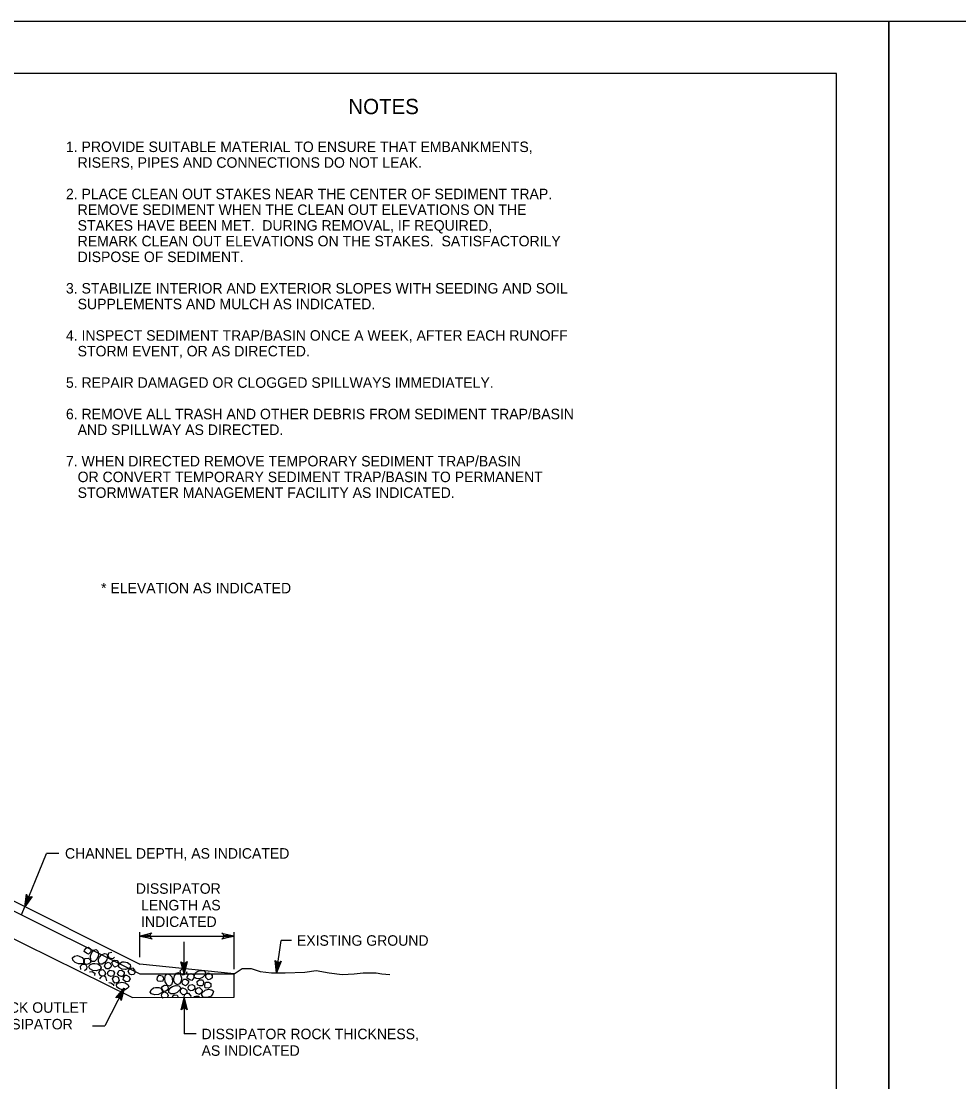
# Model space of a CAD drawing. Extents: x 636462 to 639890, y 299944 to 300538.
# Drawn here: x 637895.9 to 638163.9, y 300235 to 300538.4 of the extents above; entities that cross this region are included whole.
import ezdxf

# ---------------------------------------------------------------- set-up
doc = ezdxf.new("R2010")
doc.units = 0
for name, color, linetype in [('1', 7, 'Continuous'), ('Default', 7, 'Continuous'), ('PLT-BNDY', 7, 'Continuous')]:
    doc.layers.add(name, color=color, linetype=linetype)

msp = doc.modelspace()

# ---------------------------------------------------------------- linework, layer by layer
at = {"layer": '1'}
msp.add_lwpolyline([(638128.91, 299959.45), (638128.91, 300523.45), (637342.91, 300523.45), (637342.91, 299959.45), (638128.91, 299959.45), (638128.91, 299985.81), (637928.91, 299985.81), (637928.91, 300050.49), (638128.91, 300050.49), (638128.91, 300079.45), (637928.91, 300079.45), (637928.91, 299959.45), (638007.72, 299959.45), (638007.72, 299985.81), (638007.72, 299959.45), (638084.72, 299959.45), (638084.72, 299985.81), (638084.72, 299973.49), (638128.91, 299973.49)], dxfattribs=at)
at = {"layer": 'Default'}
for p, q in [((637788.44, 300339.34), (637929.75, 300268.68)), ((637804.16, 300328.69), (637929.74, 300265.89)), ((637801.63, 300321.37), (637927.67, 300259.18)), ((637895.93, 300282.8), (637903.13, 300300.35)), ((637906.63, 300300.35), (637903.13, 300300.35)), ((637929.75, 300270.69), (637929.75, 300277.85)), ((637929.75, 300276.72), (637956.7, 300276.72)), ((637956.7, 300267.25), (637956.7, 300277.85)), ((637913.9, 300272.27), (637913.95, 300272.69)), ((637913.95, 300272.69), (637914.39, 300273.28)), ((637914.39, 300273.28), (637915.06, 300273.51)), ((637915.06, 300273.51), (637915.8, 300272.95)), ((637915.8, 300272.95), (637915.76, 300272.19)), ((637916, 300271.97), (637916.64, 300272.69)), ((637916.64, 300272.69), (637917.28, 300272.83)), ((637917.28, 300272.83), (637917.77, 300272.36)), ((637942.42, 300265.89), (637942.42, 300275.03)), ((637968.83, 300266.17), (637970.18, 300275.44)), ((637973.18, 300275.44), (637970.18, 300275.44)), ((637910.51, 300270.5), (637911.07, 300270.95)), ((637910.62, 300269.84), (637910.51, 300270.5)), ((637911.29, 300269.19), (637910.62, 300269.84)), ((637911.07, 300270.95), (637911.94, 300271.13)), ((637911.94, 300271.13), (637912.45, 300270.98)), ((637912.45, 300270.98), (637913.29, 300270.55)), ((637913.29, 300270.55), (637913.89, 300269.81)), ((637913.76, 300269.1), (637913.8, 300269.73)), ((637913.8, 300269.73), (637914.1, 300270.26)), ((637913.89, 300269.81), (637913.88, 300269.18)), ((637914.52, 300271.78), (637913.9, 300272.27)), ((637914.1, 300270.26), (637915.05, 300270.36)), ((637915.13, 300271.52), (637914.52, 300271.78)), ((637915.05, 300270.36), (637915.62, 300269.86)), ((637915.76, 300272.19), (637915.13, 300271.52)), ((637915.62, 300269.86), (637915.65, 300269.04)), ((637915.66, 300271.04), (637916, 300271.97)), ((637915.8, 300269.82), (637915.66, 300271.04)), ((637916.18, 300269.4), (637915.8, 300269.82)), ((637916.82, 300269.46), (637916.18, 300269.4)), ((637917.5, 300270.13), (637916.82, 300269.46)), ((637917.88, 300270.95), (637917.5, 300270.13)), ((637917.77, 300272.36), (637918, 300271.48)), ((637918, 300271.48), (637917.88, 300270.95)), ((637917.96, 300270.11), (637918.25, 300270.64)), ((637917.98, 300269.29), (637917.96, 300270.11)), ((637918.25, 300270.64), (637918.85, 300271.34)), ((637918.85, 300271.34), (637919.67, 300271.75)), ((637919.67, 300271.75), (637920.28, 300271.58)), ((637920.34, 300269.9), (637919.75, 300269.11)), ((637920.28, 300271.58), (637920.54, 300271.09)), ((637920.54, 300271.09), (637920.34, 300269.9)), ((637920.7, 300271.01), (637920.93, 300271.87)), ((637921.1, 300270.36), (637920.7, 300271.01)), ((637920.93, 300271.87), (637921.72, 300272.07)), ((637922.07, 300270.24), (637921.1, 300270.36)), ((637921.9, 300269.33), (637922.57, 300269.78)), ((637922.5, 300270.65), (637922.07, 300270.24)), ((637922.57, 300269.78), (637923.32, 300269.71)), ((637923.32, 300269.71), (637923.78, 300268.95)), ((637912.23, 300268.76), (637911.29, 300269.19)), ((637913.43, 300268.8), (637912.23, 300268.76)), ((637912.84, 300268.07), (637913.37, 300268.64)), ((637912.86, 300267.18), (637912.84, 300268.07)), ((637913.37, 300268.64), (637914.19, 300268.64)), ((637913.88, 300269.18), (637913.43, 300268.8)), ((637914.31, 300268.62), (637913.76, 300269.1)), ((637914.55, 300267.26), (637913.99, 300266.72)), ((637914.19, 300268.64), (637914.59, 300267.93)), ((637914.95, 300268.63), (637914.31, 300268.62)), ((637914.59, 300267.93), (637914.55, 300267.26)), ((637915.65, 300269.04), (637914.95, 300268.63)), ((637915.17, 300267.89), (637915.52, 300268.49)), ((637915.45, 300267.31), (637915.17, 300267.89)), ((637915.4, 300266.43), (637916.14, 300266.57)), ((637916.3, 300266.85), (637915.45, 300267.31)), ((637915.52, 300268.49), (637916.32, 300268.9)), ((637916.14, 300266.57), (637916.94, 300266.1)), ((637917.28, 300266.72), (637916.3, 300266.85)), ((637916.32, 300268.9), (637916.87, 300268.9)), ((637916.87, 300268.9), (637917.76, 300268.72)), ((637918.44, 300267.13), (637917.28, 300266.72)), ((637917.76, 300268.72), (637918.56, 300268.21)), ((637918.31, 300268.68), (637917.98, 300269.29)), ((637918.08, 300266.29), (637918.45, 300266.95)), ((637918.96, 300268.64), (637918.31, 300268.68)), ((637918.76, 300267.59), (637918.44, 300267.13)), ((637918.45, 300266.95), (637919.24, 300267.17)), ((637918.56, 300268.21), (637918.76, 300267.59)), ((637919.75, 300269.11), (637918.96, 300268.64)), ((637919.24, 300267.17), (637919.79, 300266.57)), ((637919.69, 300268.14), (637919.92, 300268.83)), ((637920.22, 300267.35), (637919.69, 300268.14)), ((637919.79, 300266.57), (637919.95, 300265.95)), ((637919.92, 300268.83), (637920.69, 300269.26)), ((637920.93, 300267.38), (637920.22, 300267.35)), ((637920.5, 300266.01), (637920.7, 300266.58)), ((637920.69, 300269.26), (637921.26, 300268.95)), ((637920.7, 300266.58), (637921.21, 300266.99)), ((637921.52, 300267.84), (637920.93, 300267.38)), ((637921.21, 300266.99), (637922.16, 300266.77)), ((637921.26, 300268.95), (637921.68, 300268.21)), ((637921.68, 300268.21), (637921.52, 300267.84)), ((637921.74, 300269.01), (637921.9, 300269.33)), ((637922.15, 300268.26), (637921.74, 300269.01)), ((637922.59, 300267.81), (637922.15, 300268.26)), ((637922.16, 300266.77), (637922.5, 300266.16)), ((637923.44, 300268.23), (637922.59, 300267.81)), ((637923.4, 300266), (637923.83, 300266.84)), ((637923.78, 300268.95), (637923.44, 300268.23)), ((637923.63, 300268.31), (637924, 300268.9)), ((637923.91, 300267.72), (637923.63, 300268.31)), ((637923.83, 300266.84), (637924.55, 300266.98)), ((637924.71, 300267.26), (637923.91, 300267.72)), ((637924, 300268.9), (637924.71, 300269.31)), ((637924.55, 300266.98), (637925.3, 300266.51)), ((637924.71, 300269.31), (637925.31, 300269.32)), ((637925.69, 300267.13), (637924.71, 300267.26)), ((637925.3, 300266.51), (637925.3, 300265.86)), ((637925.31, 300269.32), (637926.22, 300269.14)), ((637926.82, 300267.54), (637925.69, 300267.13)), ((637926.22, 300269.14), (637926.97, 300268.62)), ((637926.46, 300266.7), (637926.83, 300267.36)), ((637926.83, 300265.79), (637926.46, 300266.7)), ((637927.12, 300268), (637926.82, 300267.54)), ((637926.83, 300267.36), (637927.7, 300267.58)), ((637926.97, 300268.62), (637927.12, 300268)), ((637927.7, 300267.58), (637928.25, 300266.98)), ((637928.41, 300266.37), (637928.09, 300265.72)), ((637928.25, 300266.98), (637928.41, 300266.37)), ((637956.7, 300265.89), (637929.75, 300268.68)), ((637941.28, 300266.8), (637941.89, 300267.35)), ((637941.48, 300265.94), (637941.28, 300266.8)), ((637943.24, 300266.46), (637943.06, 300265.91)), ((637945.82, 300266.33), (637946.35, 300266.62)), ((637946.35, 300266.62), (637947.23, 300266.89)), ((637947.23, 300266.89), (637948.14, 300266.79)), ((637948.14, 300266.79), (637948.57, 300266.31)), ((637916.94, 300266.1), (637916.82, 300265.45)), ((637918.4, 300265.38), (637918.08, 300266.29)), ((637918.29, 300264.52), (637918.88, 300265.27)), ((637918.98, 300265.2), (637918.4, 300265.38)), ((637918.88, 300265.27), (637919.5, 300265.4)), ((637919.6, 300265.31), (637918.98, 300265.2)), ((637919.5, 300265.4), (637919.97, 300265.05)), ((637919.95, 300265.95), (637919.6, 300265.31)), ((637919.97, 300265.05), (637920.27, 300263.89)), ((637920.8, 300265.38), (637920.5, 300266.01)), ((637921.45, 300265.17), (637920.8, 300265.38)), ((637920.89, 300263.47), (637921.5, 300263.33)), ((637922.21, 300265.3), (637921.45, 300265.17)), ((637921.5, 300263.33), (637922.22, 300262.89)), ((637921.97, 300264.52), (637922.36, 300265.09)), ((637922.1, 300263.86), (637921.97, 300264.52)), ((637922.58, 300263.25), (637922.1, 300263.86)), ((637922.5, 300266.16), (637922.21, 300265.3)), ((637922.36, 300265.09), (637922.96, 300265.2)), ((637923.47, 300263.42), (637922.58, 300263.25)), ((637922.96, 300265.2), (637923.57, 300264.95)), ((637923.38, 300263.22), (637924.59, 300263.55)), ((637923.78, 300265.39), (637923.4, 300266)), ((637923.84, 300264.02), (637923.47, 300263.42)), ((637923.57, 300264.95), (637923.84, 300264.02)), ((637924.47, 300265.1), (637923.78, 300265.39)), ((637924.86, 300265.14), (637924.47, 300265.1)), ((637924.59, 300263.55), (637925.6, 300263.33)), ((637925.3, 300265.86), (637924.86, 300265.14)), ((637924.96, 300264.15), (637925.13, 300264.75)), ((637925.74, 300263.61), (637924.96, 300264.15)), ((637925.13, 300264.75), (637925.6, 300265.48)), ((637925.6, 300265.48), (637925.95, 300265.49)), ((637925.6, 300263.33), (637926.35, 300262.81)), ((637926.54, 300263.67), (637925.74, 300263.61)), ((637925.95, 300265.49), (637926.66, 300265.13)), ((637926.97, 300264.44), (637926.54, 300263.67)), ((637926.66, 300265.13), (637926.97, 300264.44)), ((637927.39, 300265.62), (637926.83, 300265.79)), ((637928.09, 300265.72), (637927.39, 300265.62)), ((637929.74, 300265.89), (637956.7, 300265.89)), ((637934.74, 300264.24), (637934.85, 300264.95)), ((637934.89, 300263.84), (637934.74, 300264.24)), ((637934.85, 300264.95), (637935.33, 300265.48)), ((637935.67, 300263.7), (637934.89, 300263.84)), ((637935.33, 300265.48), (637936.25, 300265.33)), ((637936.34, 300263.76), (637935.67, 300263.7)), ((637936.25, 300265.33), (637936.57, 300264.65)), ((637936.57, 300264.65), (637936.34, 300263.76)), ((637936.89, 300264.57), (637937.11, 300265.5)), ((637937.02, 300263.59), (637936.89, 300264.57)), ((637937.72, 300262.58), (637937.02, 300263.59)), ((637937.11, 300265.5), (637937.6, 300265.93)), ((637937.6, 300265.93), (637938.27, 300265.75)), ((637938.27, 300265.75), (637938.88, 300265.08)), ((637939.08, 300263.65), (637938.79, 300262.74)), ((637938.88, 300265.08), (637939.02, 300264.55)), ((637939.02, 300264.55), (637939.08, 300263.65)), ((637939.49, 300263.85), (637939.5, 300264.45)), ((637939.89, 300263.14), (637939.49, 300263.85)), ((637939.5, 300264.45), (637939.7, 300265.36)), ((637939.7, 300265.36), (637940.23, 300266.1)), ((637940.23, 300266.1), (637940.85, 300266.24)), ((637940.85, 300266.24), (637941.31, 300265.93)), ((637941.55, 300263.81), (637941.07, 300263.02)), ((637941.31, 300265.93), (637941.69, 300264.79)), ((637942.14, 300265.56), (637941.48, 300265.94)), ((637941.69, 300264.79), (637941.55, 300263.81)), ((637941.83, 300263.65), (637942.3, 300264.39)), ((637941.95, 300262.92), (637941.83, 300263.65)), ((637943.06, 300265.91), (637942.14, 300265.56)), ((637942.3, 300264.39), (637942.95, 300264.38)), ((637942.95, 300264.38), (637943.67, 300263.93)), ((637943.33, 300265.02), (637943.71, 300265.73)), ((637943.34, 300264.67), (637943.33, 300265.02)), ((637944.06, 300264.19), (637943.34, 300264.67)), ((637943.7, 300263.53), (637943.4, 300262.84)), ((637943.67, 300263.93), (637943.7, 300263.53)), ((637943.71, 300265.73), (637944.4, 300266.02)), ((637944.66, 300264.01), (637944.06, 300264.19)), ((637944.4, 300266.02), (637945.17, 300265.57)), ((637945.22, 300264.77), (637944.66, 300264.01)), ((637945.17, 300265.57), (637945.22, 300264.77)), ((637945.34, 300264.94), (637945.39, 300265.63)), ((637945.87, 300264.55), (637945.34, 300264.94)), ((637945.39, 300265.63), (637945.82, 300266.33)), ((637946.79, 300264.52), (637945.87, 300264.55)), ((637946.21, 300263.74), (637946.78, 300264.19)), ((637946.23, 300262.78), (637946.21, 300263.74)), ((637946.78, 300264.19), (637947.66, 300264.14)), ((637947.71, 300264.87), (637946.79, 300264.52)), ((637947.66, 300264.14), (637947.97, 300263.57)), ((637948.52, 300265.76), (637947.71, 300264.87)), ((637947.97, 300263.57), (637947.92, 300262.72)), ((637948.34, 300262.51), (637948.41, 300263.37)), ((637948.41, 300263.37), (637948.71, 300263.55)), ((637948.57, 300266.31), (637948.52, 300265.76)), ((637948.6, 300264.85), (637948.61, 300265.61)), ((637949.35, 300264.22), (637948.6, 300264.85)), ((637948.61, 300265.61), (637949.27, 300266.21)), ((637948.71, 300263.55), (637949.52, 300263.56)), ((637949.27, 300266.21), (637950.04, 300265.95)), ((637949.93, 300264.34), (637949.35, 300264.22)), ((637949.52, 300263.56), (637950.11, 300263.11)), ((637950.49, 300264.76), (637949.93, 300264.34)), ((637950.04, 300265.95), (637950.47, 300265.47)), ((637950.47, 300265.47), (637950.49, 300264.76)), ((637956.7, 300259.19), (637956.7, 300265.89)), ((637925.26, 300261.78), (637919.74, 300251.07)), ((637922.22, 300262.89), (637922.24, 300262.49)), ((637923.08, 300262.78), (637923.38, 300263.22)), ((637923.16, 300262.13), (637923.08, 300262.78)), ((637923.96, 300261.6), (637923.16, 300262.13)), ((637924.82, 300261.36), (637923.96, 300261.6)), ((637925.35, 300261.26), (637924.82, 300261.36)), ((637926.13, 300261.7), (637925.35, 300261.26)), ((637926.61, 300262.2), (637926.13, 300261.7)), ((637926.35, 300262.81), (637926.61, 300262.2)), ((637932.74, 300260.67), (637933.02, 300261.34)), ((637933.15, 300260.15), (637932.74, 300260.67)), ((637933.02, 300261.34), (637933.71, 300261.91)), ((637933.71, 300261.91), (637934.22, 300262.02)), ((637934.22, 300262.02), (637935.16, 300262.04)), ((637936.11, 300260.56), (637935.07, 300259.96)), ((637935.16, 300262.04), (637936.04, 300261.67)), ((637935.94, 300259.64), (637936.14, 300260.38)), ((637936, 300261.55), (637936.02, 300262.16)), ((637936.27, 300260.98), (637936, 300261.55)), ((637936.02, 300262.16), (637936.81, 300262.7)), ((637936.04, 300261.67), (637936.33, 300261.1)), ((637936.33, 300261.1), (637936.11, 300260.56)), ((637936.14, 300260.38), (637936.86, 300260.77)), ((637936.98, 300260.81), (637936.27, 300260.98)), ((637936.81, 300262.7), (637937.55, 300262.52)), ((637936.86, 300260.77), (637937.55, 300260.34)), ((637937.53, 300261.12), (637936.98, 300260.81)), ((637937.97, 300261.82), (637937.53, 300261.12)), ((637937.55, 300262.52), (637937.97, 300261.82)), ((637937.55, 300260.34), (637937.83, 300259.72)), ((637938.25, 300262.38), (637937.72, 300262.58)), ((637938.08, 300260.58), (637938.11, 300261.27)), ((637938.6, 300260.19), (637938.08, 300260.58)), ((637938.11, 300261.27), (637938.62, 300262.01)), ((637938.79, 300262.74), (637938.25, 300262.38)), ((637938.62, 300262.01), (637939.11, 300262.27)), ((637939.11, 300262.27), (637939.97, 300262.53)), ((637940.49, 300260.54), (637939.57, 300260.19)), ((637940.48, 300262.75), (637939.89, 300263.14)), ((637939.97, 300262.53), (637940.92, 300262.46)), ((637941.07, 300263.02), (637940.48, 300262.75)), ((637941.32, 300261.44), (637940.49, 300260.54)), ((637940.92, 300262.46), (637941.39, 300262.01)), ((637941.39, 300262.01), (637941.32, 300261.44)), ((637941.4, 300260.53), (637941.41, 300261.29)), ((637942.11, 300259.88), (637941.4, 300260.53)), ((637941.41, 300261.29), (637942.01, 300261.86)), ((637942.79, 300262.48), (637941.95, 300262.92)), ((637942.01, 300261.86), (637942.78, 300261.59)), ((637942.58, 300260.02), (637943.07, 300260.42)), ((637943.21, 300260.39), (637942.71, 300260)), ((637942.78, 300261.59), (637943.21, 300261.12)), ((637943.4, 300262.84), (637942.79, 300262.48)), ((637943.07, 300260.42), (637943.65, 300260.33)), ((637943.21, 300261.12), (637943.21, 300260.39)), ((637943.58, 300262.02), (637943.83, 300262.63)), ((637943.67, 300261.43), (637943.58, 300262.02)), ((637943.65, 300260.33), (637944.47, 300259.46)), ((637944.23, 300261.02), (637943.67, 300261.43)), ((637943.83, 300262.63), (637944.77, 300262.89)), ((637944.9, 300261.14), (637944.23, 300261.02)), ((637944.77, 300262.89), (637945.36, 300262.5)), ((637945.51, 300261.61), (637944.9, 300261.14)), ((637945.36, 300262.5), (637945.51, 300261.61)), ((637945.66, 300260.81), (637945.74, 300261.5)), ((637946.09, 300260.29), (637945.66, 300260.81)), ((637945.74, 300261.5), (637946.22, 300261.88)), ((637946.8, 300259.98), (637946.09, 300260.29)), ((637946.22, 300261.88), (637946.87, 300261.95)), ((637946.85, 300262.43), (637946.23, 300262.78)), ((637947.51, 300260.55), (637946.8, 300259.98)), ((637947.59, 300262.5), (637946.85, 300262.43)), ((637946.87, 300261.95), (637947.55, 300261.25)), ((637947.46, 300259.8), (637947.52, 300260.33)), ((637947.55, 300261.25), (637947.51, 300260.55)), ((637947.52, 300260.33), (637948.43, 300261.19)), ((637947.92, 300262.72), (637947.59, 300262.5)), ((637948.48, 300261.89), (637948.34, 300262.51)), ((637948.43, 300261.19), (637949.43, 300261.47)), ((637949.42, 300261.79), (637948.48, 300261.89)), ((637950.09, 300262.22), (637949.42, 300261.79)), ((637949.43, 300261.47), (637950.34, 300261.37)), ((637950.11, 300263.11), (637950.09, 300262.22)), ((637950.67, 300260.29), (637950.19, 300259.54)), ((637950.34, 300261.37), (637950.85, 300260.95)), ((637950.85, 300260.95), (637950.67, 300260.29)), ((637927.67, 300259.18), (637956.7, 300259.19)), ((637934.05, 300259.89), (637933.15, 300260.15)), ((637935.07, 300259.96), (637934.05, 300259.89)), ((637936.38, 300258.86), (637935.94, 300259.64)), ((637937.83, 300259.72), (637937.59, 300258.99)), ((637939.57, 300260.19), (637938.6, 300260.19)), ((637938.97, 300259.39), (637939.56, 300259.86)), ((637939.56, 300259.86), (637940.48, 300259.83)), ((637940.48, 300259.83), (637940.69, 300259.2)), ((637942.71, 300260), (637942.11, 300259.88)), ((637942.42, 300259.08), (637942.58, 300260.02)), ((637942.42, 300259.08), (637942.42, 300248.7)), ((637945.21, 300259.38), (637945.81, 300259.54)), ((637945.81, 300259.54), (637946.66, 300259.49)), ((637946.66, 300259.49), (637946.86, 300259.15)), ((637947.84, 300259.27), (637947.46, 300259.8)), ((637948.8, 300259.17), (637947.84, 300259.27)), ((637949.67, 300259.37), (637948.8, 300259.17)), ((637950.19, 300259.54), (637949.67, 300259.37)), ((637916.25, 300251.07), (637919.74, 300251.07)), ((637945.92, 300248.7), (637942.42, 300248.7))]:
    msp.add_line(p, q, dxfattribs=at)
for points in [[(637898.68, 300287.88), (637898.99, 300288.04), (637896.88, 300285.12), (637898.68, 300287.88), (637898.26, 300287.83), (637896.88, 300285.12), (637897.77, 300288.02), (637897.49, 300288.33), (637896.88, 300285.12), (637897.36, 300288.69), (637897.49, 300288.33)], [(637932.98, 300276.08), (637933.25, 300275.86), (637929.75, 300276.72), (637932.98, 300276.08), (637932.79, 300276.46), (637929.75, 300276.72), (637932.78, 300276.98), (637932.96, 300277.35), (637929.75, 300276.72), (637933.24, 300277.61), (637932.96, 300277.35)], [(637953.47, 300277.36), (637953.2, 300277.58), (637956.7, 300276.72), (637953.47, 300277.36), (637953.67, 300276.98), (637956.7, 300276.72), (637953.67, 300276.46), (637953.49, 300276.09), (637956.7, 300276.72), (637953.21, 300275.83), (637953.49, 300276.09)], [(637943.06, 300269.12), (637943.28, 300269.39), (637942.42, 300265.89), (637943.06, 300269.12), (637942.69, 300268.92), (637942.42, 300265.89), (637942.16, 300268.92), (637941.79, 300269.1), (637942.42, 300265.89), (637941.53, 300269.38), (637941.79, 300269.1)], [(637969.95, 300269.26), (637970.22, 300269.5), (637968.83, 300266.17), (637969.95, 300269.26), (637969.55, 300269.13), (637968.83, 300266.17), (637969.04, 300269.2), (637968.69, 300269.44), (637968.83, 300266.17), (637968.49, 300269.76), (637968.69, 300269.44)], [(637956.7, 300265.89), (637959.04, 300267.47), (637961.59, 300267.47), (637964.14, 300266.6), (637967.39, 300266.17), (637971.34, 300266.17), (637976.91, 300266.38), (637980.16, 300266.82), (637983.87, 300266.17), (637987.58, 300265.73), (637991.07, 300265.95), (637993.61, 300266.17), (637997.33, 300266.17), (637998.96, 300265.95), (638001.27, 300265.73)], [(637923.21, 300259.2), (637922.89, 300259.07), (637925.26, 300261.78), (637923.21, 300259.2), (637923.63, 300259.21), (637925.26, 300261.78), (637924.1, 300258.97), (637924.35, 300258.64), (637925.26, 300261.78), (637924.44, 300258.27), (637924.35, 300258.64)], [(637941.78, 300255.84), (637941.56, 300255.57), (637942.42, 300259.08), (637941.78, 300255.84), (637942.16, 300256.04), (637942.42, 300259.08), (637942.68, 300256.05), (637943.06, 300255.86), (637942.42, 300259.08), (637943.31, 300255.58), (637943.06, 300255.86)]]:
    msp.add_lwpolyline(points, dxfattribs=at)
at = {"layer": 'PLT-BNDY'}
for points in [[(637302.91, 300538.45), (638143.91, 300538.45), (638143.91, 299944.45), (637302.91, 299944.45)], [(638143.91, 300538.45), (638984.91, 300538.45), (638984.91, 299944.45), (638143.91, 299944.45)]]:
    msp.add_lwpolyline(points, close=True, dxfattribs=at)

# ---------------------------------------------------------------- texts
at = {"layer": 'Default'}
for s, height, p in [('NOTES', 4.372, (637989.4, 300511.86)), ('1. PROVIDE SUITABLE MATERIAL TO ENSURE THAT EMBANKMENTS,', 2.998, (637908.65, 300501.02)), ('   RISERS, PIPES AND CONNECTIONS DO NOT LEAK.', 2.998, (637908.65, 300496.52)), ('2. PLACE CLEAN OUT STAKES NEAR THE CENTER OF SEDIMENT TRAP.', 2.998, (637908.65, 300487.53)), ('   REMOVE SEDIMENT WHEN THE CLEAN OUT ELEVATIONS ON THE', 2.998, (637908.65, 300483.03)), ('   STAKES HAVE BEEN MET.  DURING REMOVAL, IF REQUIRED, ', 2.998, (637908.65, 300478.53)), ('   REMARK CLEAN OUT ELEVATIONS ON THE STAKES.  SATISFACTORILY', 2.998, (637908.65, 300474.04)), ('   DISPOSE OF SEDIMENT.', 2.998, (637908.65, 300469.54)), ('3. STABILIZE INTERIOR AND EXTERIOR SLOPES WITH SEEDING AND SOIL', 2.998, (637908.65, 300460.54)), ('   SUPPLEMENTS AND MULCH AS INDICATED.', 2.998, (637908.65, 300456.05)), ('4. INSPECT SEDIMENT TRAP/BASIN ONCE A WEEK, AFTER EACH RUNOFF', 2.998, (637908.65, 300447.05)), ('   STORM EVENT, OR AS DIRECTED.', 2.998, (637908.65, 300442.56)), ('5. REPAIR DAMAGED OR CLOGGED SPILLWAYS IMMEDIATELY.', 2.998, (637908.65, 300433.56)), ('6. REMOVE ALL TRASH AND OTHER DEBRIS FROM SEDIMENT TRAP/BASIN', 2.998, (637908.65, 300424.57)), ('   AND SPILLWAY AS DIRECTED.', 2.998, (637908.65, 300420.07)), ('7. WHEN DIRECTED REMOVE TEMPORARY SEDIMENT TRAP/BASIN ', 2.998, (637908.65, 300411.08)), ('   OR CONVERT TEMPORARY SEDIMENT TRAP/BASIN TO PERMANENT', 2.998, (637908.65, 300406.58)), ('   STORMWATER MANAGEMENT FACILITY AS INDICATED.', 2.998, (637908.65, 300402.08)), ('* ELEVATION AS INDICATED', 2.998, (637918.68, 300374.77)), ('CHANNEL DEPTH, AS INDICATED', 2.998, (637908.38, 300298.86)), ('DISSIPATOR', 2.998, (637928.63, 300288.81)), ('LENGTH AS', 2.998, (637930.15, 300284.06)), ('INDICATED', 2.998, (637930.13, 300279.31)), ('EXISTING GROUND', 2.998, (637974.68, 300273.94)), ('ROCK OUTLET', 2.998, (637886.32, 300254.76)), ('DISSIPATOR', 2.998, (637886.32, 300250.01)), ('DISSIPATOR ROCK THICKNESS,', 2.998, (637947.42, 300247.2)), ('AS INDICATED', 2.998, (637947.42, 300242.45))]:
    msp.add_text(s, height=height, dxfattribs=at).set_placement(p)

doc.saveas('drawing.dxf')
